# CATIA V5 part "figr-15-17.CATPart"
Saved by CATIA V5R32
Part number: Part1
Bounding box of the stored display mesh (mm): x -46.56 to 46.56, y -26.965 to 25.965, z 0 to 40
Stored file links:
  D:\PROJECTS\Project 2022\CATIA V5 6R 2022\Resources\Part Files\c15_catia_v5_6r2022_prt\figr-15-17.CATPart
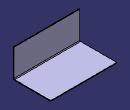
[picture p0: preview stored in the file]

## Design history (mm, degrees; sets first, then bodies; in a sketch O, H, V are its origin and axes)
SheetMetalParameters1: Thickness 1, BendRadius 1, KFactor 0.325257 {= log(min(100,max(20*SheetMetalParameters1.BendRadius,SheetMetalParameters1.Thickness)/SheetMetalParameters1.Thickness))/log(100)/2}, ReliefRadialLength 1, ReliefAxialLength 2, MinimumBendRadius 0
Body1 (main body)
  Sketch1 on xy-plane, origin (0, 0, 0), H (1, 0, 0), V (0, 1, 0)
    line L1 (-46.5596, 25.9646) -> (46.5596, 25.9646)
    line L2 (46.5596, 25.9646) -> (46.5596, -25.9646)
    line L3 (46.5596, -25.9646) -> (-46.5596, -25.9646)
    line L4 (-46.5596, -25.9646) -> (-46.5596, 25.9646)
    horizontal: L1 H, L3 H
    vertical: L2 V, L4 V
    symmetry: L1 L3 H, L4 L2 V
  Wall1: Thickness 1, Profile Sketch1
  d_NewWallOnEdge1: NewWallOnEdge_Edge edge [face of Wall1 | face of Wall1], NewWallOnEdge_Length 40, NewWallOnEdge_HeightLimitOffset 0, NewWallOnEdge_WidthOffset1 0, NewWallOnEdge_WidthOffset2 0, NewWallOnEdge_Angle 90, NewWallOnEdge_BendRadiusValue 1 {= SheetMetalParameters1.BendRadius}, NewWallOnEdge_BendTable SheetMetalParameters1, KFacteur 0.325257 {= log(min(100,max(20*d_NewWallOnEdge1.Radius,SheetMetalParameters1.Thickness)/SheetMetalParameters1.Thickness))/log(100)/2}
